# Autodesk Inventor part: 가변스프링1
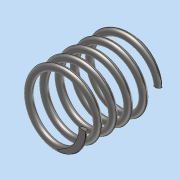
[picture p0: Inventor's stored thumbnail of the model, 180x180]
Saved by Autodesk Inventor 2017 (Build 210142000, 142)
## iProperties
Part Number: 가변스프링1
Material: 스테인레스 스틸
Document SubType Name: Modeling
Designer: MRC
Density: 8 g/cm^3
Appearance: 반연마
Mass: 6.97832 g
Surface Area: 17.713 cm^2
Volume: 0.872289 cm^3
Author: MRC
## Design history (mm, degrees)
sketch "스케치1"
  geometry: L1 (0, 0)-(0, 22.5); L2 (0, 0)-(9, 0); L3 (0, 22.5)-(9, 22.5); C1 r 1 at (9, 0)
  constraints: 6 end point, 2 horizontal, 1 centre point, 1 coincident, 1 vertical
  dimensions: "d0" = 22.5 distance of L1.start L1.end (derived); "d1" = 9 distance of L1.start L2.end; "d2" = 9 distance of L1.end L3.end; "d3" = 2 diameter of C1
feature "코일1" sketch "스케치1" pitch "d4" = 10; turns "d6" = 5; dims "d5" = 22.5 (= d0), "d7" = 0, angle "d8" = 90 deg, angle "d9" = 90 deg, "d10" = 0, "d11" = 0
sketch "스케치2"
  geometry: L1 (22.5, 16.059)-(0, 16.059); L2 (0, 16.059)-(0, -16.059); L3 (0, -16.059)-(22.5, -16.059); L4 (22.5, -16.059)-(22.5, 16.059); 2 further points
  constraints: 8 end point, 2 parallel, 1 coincident, 1 horizontal, 1 midpoint, 1 perpendicular
  dimensions: "d12" = 22.5 distance of L2.end L3.end (= d0); "d13" = 32.11845 distance of L3.end L1.start
extrude "돌출1" sketch "스케치2" stored distance "d14" = 0; taper "d15" = 0 deg
node "솔리드1"
